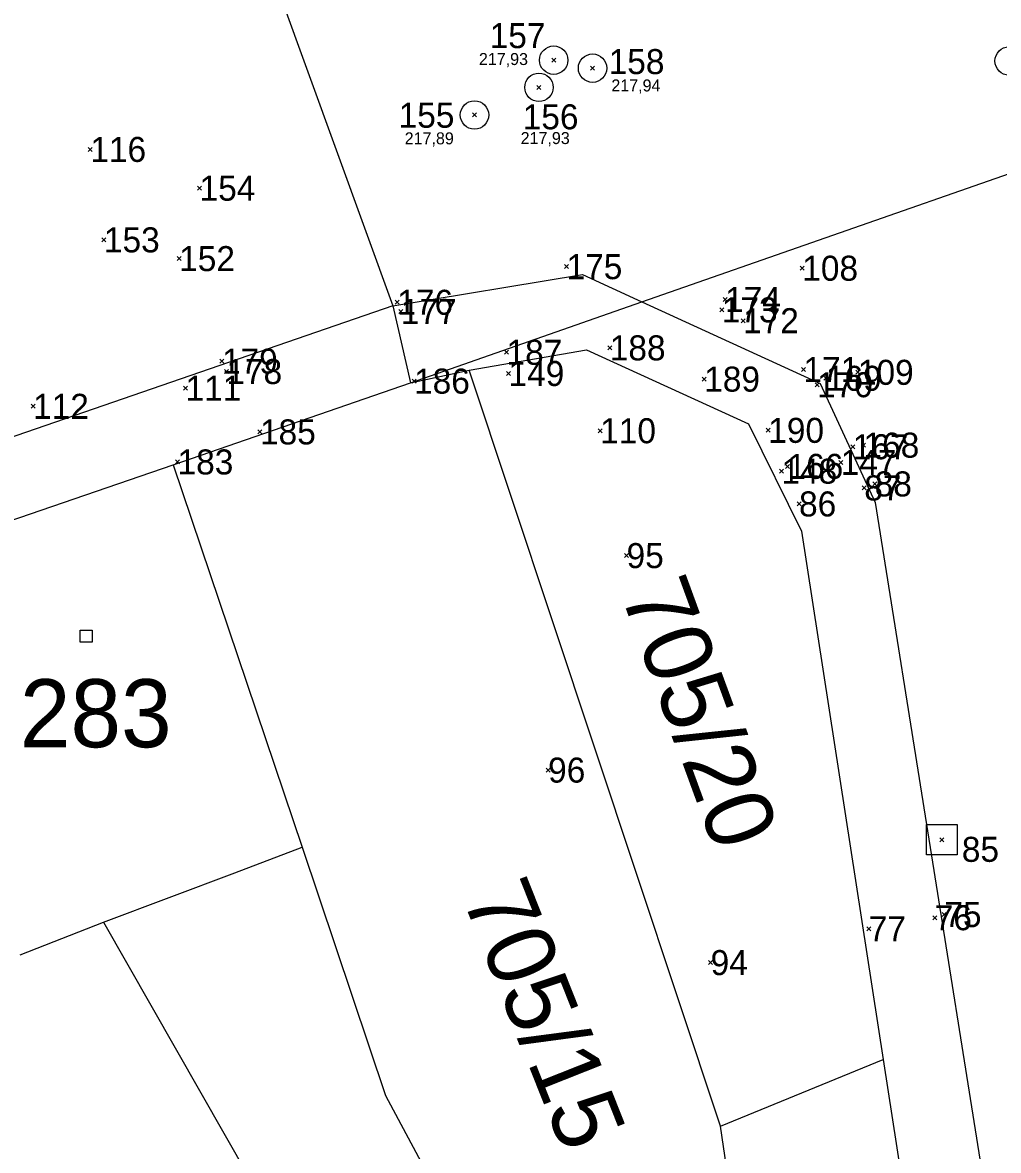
# Model space of a CAD drawing. Extents: x -711879 to -711361, y -1048782 to -1048177.
# Drawn here: x -711669.86 to -711645.48, y -1048569.9 to -1048541.72 of the extents above; entities that cross this region are included whole.
import ezdxf

# ---------------------------------------------------------------- set-up
doc = ezdxf.new("R2010")
doc.units = 0
for name, color, linetype in [('body', 7, 'Continuous'), ('kresba', 7, 'Continuous'), ('Vrstva 1', 7, 'Continuous'), ('Vrstva 14', 7, 'Continuous'), ('Vrstva 15', 7, 'Continuous'), ('Vrstva 2', 7, 'Continuous'), ('Vrstva 20', 7, 'Continuous'), ('Vrstva 25', 7, 'Continuous'), ('Vrstva 41', 7, 'Continuous'), ('Vrstva 46', 7, 'Continuous'), ('výšky', 7, 'Continuous')]:
    doc.layers.add(name, color=color, linetype=linetype)

msp = doc.modelspace()

# ---------------------------------------------------------------- linework, layer by layer
at = {"layer": 'kresba'}
msp.add_lwpolyline([(-711647.275, -1048561.76), (-711646.505, -1048561.76), (-711646.505, -1048562.52), (-711647.275, -1048562.52)], close=True, dxfattribs=at)
for centre in [(-711656.59, -1048542.66), (-711655.62, -1048542.86), (-711645.21, -1048542.68), (-711656.96, -1048543.34), (-711658.57, -1048544.03)]:
    msp.add_circle(centre, 0.355, dxfattribs=at)
at = {"layer": 'Vrstva 1'}
for p, q in [((-711664.62, -1048537.77), (-711660.61, -1048548.8)), ((-711654.39, -1048548.7), (-711637.91, -1048542.94)), ((-711660.61, -1048548.8), (-711660.17, -1048550.72)), ((-711660.17, -1048550.72), (-711654.39, -1048548.7)), ((-711654.39, -1048548.7), (-711649.93, -1048550.74)), ((-711658.7, -1048550.41), (-711655.77, -1048549.9)), ((-711655.77, -1048549.9), (-711651.72, -1048551.75)), ((-711660.17, -1048550.72), (-711658.7, -1048550.41)), ((-711652.42, -1048569.3), (-711658.7, -1048550.41)), ((-711666.1, -1048552.77), (-711660.17, -1048550.72)), ((-711649.93, -1048550.74), (-711648.56, -1048553.71)), ((-711651.72, -1048551.75), (-711650.4, -1048554.43)), ((-711673.96, -1048555.47), (-711666.1, -1048552.77)), ((-711666.1, -1048552.77), (-711662.88, -1048562.33)), ((-711648.56, -1048553.71), (-711625.71, -1048697.17)), ((-711650.4, -1048554.43), (-711648.36, -1048567.63)), ((-711662.88, -1048562.33), (-711660.79, -1048568.53)), ((-711652.42, -1048569.3), (-711648.36, -1048567.63)), ((-711648.36, -1048567.63), (-711645.9, -1048583.49)), ((-711660.79, -1048568.53), (-711658.99, -1048571.9)), ((-711650.24, -1048584.31), (-711652.42, -1048569.3))]:
    msp.add_line(p, q, dxfattribs=at)
at = {"layer": 'Vrstva 2'}
for p, q in [((-711660.61, -1048548.8), (-711655.87, -1048548.02)), ((-711655.87, -1048548.02), (-711654.39, -1048548.7)), ((-711660.61, -1048548.8), (-711673.32, -1048553.18)), ((-711664.56, -1048562.97), (-711662.88, -1048562.33)), ((-711667.84, -1048564.2), (-711664.56, -1048562.97)), ((-711669.92, -1048565.02), (-711667.84, -1048564.2)), ((-711667.84, -1048564.2), (-711661.64, -1048575.07))]:
    msp.add_line(p, q, dxfattribs=at)
at = {"layer": 'Vrstva 20'}
for p, q in [((-711656.59, -1048542.66), (-711656.64, -1048542.61)), ((-711656.59, -1048542.66), (-711656.64, -1048542.71)), ((-711656.59, -1048542.66), (-711656.54, -1048542.61)), ((-711656.59, -1048542.66), (-711656.54, -1048542.71)), ((-711655.62, -1048542.86), (-711655.67, -1048542.81)), ((-711655.62, -1048542.86), (-711655.67, -1048542.91)), ((-711655.62, -1048542.86), (-711655.57, -1048542.81)), ((-711655.62, -1048542.86), (-711655.57, -1048542.91)), ((-711656.96, -1048543.34), (-711657.01, -1048543.29)), ((-711656.96, -1048543.34), (-711657.01, -1048543.39)), ((-711656.96, -1048543.34), (-711656.91, -1048543.29)), ((-711656.96, -1048543.34), (-711656.91, -1048543.39)), ((-711658.57, -1048544.03), (-711658.62, -1048543.98)), ((-711658.57, -1048544.03), (-711658.52, -1048543.98)), ((-711658.57, -1048544.03), (-711658.62, -1048544.08)), ((-711658.57, -1048544.03), (-711658.52, -1048544.08)), ((-711668.17, -1048544.89), (-711668.22, -1048544.84)), ((-711668.17, -1048544.89), (-711668.12, -1048544.84)), ((-711668.17, -1048544.89), (-711668.22, -1048544.94)), ((-711668.17, -1048544.89), (-711668.12, -1048544.94)), ((-711665.44, -1048545.86), (-711665.49, -1048545.81)), ((-711665.44, -1048545.86), (-711665.49, -1048545.91)), ((-711665.44, -1048545.86), (-711665.39, -1048545.81)), ((-711665.44, -1048545.86), (-711665.39, -1048545.91)), ((-711667.83, -1048547.15), (-711667.88, -1048547.1)), ((-711667.83, -1048547.15), (-711667.78, -1048547.1)), ((-711667.83, -1048547.15), (-711667.88, -1048547.2)), ((-711667.83, -1048547.15), (-711667.78, -1048547.2)), ((-711665.95, -1048547.62), (-711666, -1048547.57)), ((-711665.95, -1048547.62), (-711666, -1048547.67)), ((-711665.95, -1048547.62), (-711665.9, -1048547.57)), ((-711665.95, -1048547.62), (-711665.9, -1048547.67)), ((-711656.27, -1048547.82), (-711656.32, -1048547.77)), ((-711656.27, -1048547.82), (-711656.32, -1048547.87)), ((-711656.27, -1048547.82), (-711656.22, -1048547.77)), ((-711656.27, -1048547.82), (-711656.22, -1048547.87)), ((-711650.38, -1048547.86), (-711650.43, -1048547.81)), ((-711650.38, -1048547.86), (-711650.43, -1048547.91)), ((-711650.38, -1048547.86), (-711650.33, -1048547.81)), ((-711650.38, -1048547.86), (-711650.33, -1048547.91)), ((-711660.5, -1048548.71), (-711660.55, -1048548.66)), ((-711660.5, -1048548.71), (-711660.55, -1048548.76)), ((-711660.5, -1048548.71), (-711660.45, -1048548.66)), ((-711660.5, -1048548.71), (-711660.45, -1048548.76)), ((-711652.31, -1048548.64), (-711652.36, -1048548.59)), ((-711652.31, -1048548.64), (-711652.36, -1048548.69)), ((-711652.31, -1048548.64), (-711652.26, -1048548.59)), ((-711652.31, -1048548.64), (-711652.26, -1048548.69)), ((-711660.41, -1048548.94), (-711660.46, -1048548.89)), ((-711660.41, -1048548.94), (-711660.46, -1048548.99)), ((-711660.41, -1048548.94), (-711660.36, -1048548.89)), ((-711660.41, -1048548.94), (-711660.36, -1048548.99)), ((-711652.39, -1048548.9), (-711652.44, -1048548.85)), ((-711652.39, -1048548.9), (-711652.44, -1048548.95)), ((-711652.39, -1048548.9), (-711652.34, -1048548.85)), ((-711652.39, -1048548.9), (-711652.34, -1048548.95)), ((-711651.86, -1048549.17), (-711651.91, -1048549.12)), ((-711651.86, -1048549.17), (-711651.91, -1048549.22)), ((-711651.86, -1048549.17), (-711651.81, -1048549.12)), ((-711651.86, -1048549.17), (-711651.81, -1048549.22)), ((-711657.77, -1048549.96), (-711657.82, -1048549.91)), ((-711657.77, -1048549.96), (-711657.72, -1048549.91)), ((-711655.19, -1048549.85), (-711655.24, -1048549.8)), ((-711655.19, -1048549.85), (-711655.24, -1048549.9)), ((-711655.19, -1048549.85), (-711655.14, -1048549.8)), ((-711655.19, -1048549.85), (-711655.14, -1048549.9)), ((-711664.88, -1048550.18), (-711664.93, -1048550.13)), ((-711664.88, -1048550.18), (-711664.93, -1048550.23)), ((-711664.88, -1048550.18), (-711664.83, -1048550.13)), ((-711664.88, -1048550.18), (-711664.83, -1048550.23)), ((-711657.77, -1048549.96), (-711657.82, -1048550.01)), ((-711657.77, -1048549.96), (-711657.72, -1048550.01)), ((-711664.77, -1048550.44), (-711664.82, -1048550.39)), ((-711664.77, -1048550.44), (-711664.82, -1048550.49)), ((-711664.77, -1048550.44), (-711664.72, -1048550.39)), ((-711664.77, -1048550.44), (-711664.72, -1048550.49)), ((-711657.72, -1048550.49), (-711657.77, -1048550.44)), ((-711657.72, -1048550.49), (-711657.77, -1048550.54)), ((-711657.72, -1048550.49), (-711657.67, -1048550.44)), ((-711657.72, -1048550.49), (-711657.67, -1048550.54)), ((-711650.35, -1048550.39), (-711650.4, -1048550.34)), ((-711650.35, -1048550.39), (-711650.4, -1048550.44)), ((-711650.35, -1048550.39), (-711650.3, -1048550.34)), ((-711650.35, -1048550.39), (-711650.3, -1048550.44)), ((-711648.99, -1048550.46), (-711649.04, -1048550.41)), ((-711648.99, -1048550.46), (-711649.04, -1048550.51)), ((-711648.99, -1048550.46), (-711648.94, -1048550.41)), ((-711648.99, -1048550.46), (-711648.94, -1048550.51)), ((-711660.08, -1048550.68), (-711660.13, -1048550.63)), ((-711660.08, -1048550.68), (-711660.13, -1048550.73)), ((-711660.08, -1048550.68), (-711660.03, -1048550.63)), ((-711660.08, -1048550.68), (-711660.03, -1048550.73)), ((-711652.83, -1048550.63), (-711652.88, -1048550.58)), ((-711652.83, -1048550.63), (-711652.88, -1048550.68)), ((-711652.83, -1048550.63), (-711652.78, -1048550.58)), ((-711652.83, -1048550.63), (-711652.78, -1048550.68)), ((-711650.01, -1048550.77), (-711650.06, -1048550.72)), ((-711650.01, -1048550.77), (-711650.06, -1048550.82)), ((-711650.01, -1048550.77), (-711649.96, -1048550.72)), ((-711650.01, -1048550.77), (-711649.96, -1048550.82)), ((-711649.79, -1048550.61), (-711649.84, -1048550.56)), ((-711649.79, -1048550.61), (-711649.84, -1048550.66)), ((-711649.79, -1048550.61), (-711649.74, -1048550.56)), ((-711649.79, -1048550.61), (-711649.74, -1048550.66)), ((-711665.79, -1048550.86), (-711665.84, -1048550.81)), ((-711665.79, -1048550.86), (-711665.84, -1048550.91)), ((-711665.79, -1048550.86), (-711665.74, -1048550.81)), ((-711665.79, -1048550.86), (-711665.74, -1048550.91)), ((-711669.6, -1048551.31), (-711669.65, -1048551.26)), ((-711669.6, -1048551.31), (-711669.65, -1048551.36)), ((-711669.6, -1048551.31), (-711669.55, -1048551.26)), ((-711669.6, -1048551.31), (-711669.55, -1048551.36)), ((-711663.93, -1048551.95), (-711663.98, -1048551.9)), ((-711663.93, -1048551.95), (-711663.88, -1048551.9)), ((-711655.43, -1048551.92), (-711655.48, -1048551.87)), ((-711655.43, -1048551.92), (-711655.38, -1048551.87)), ((-711651.23, -1048551.91), (-711651.28, -1048551.86)), ((-711651.23, -1048551.91), (-711651.18, -1048551.86)), ((-711663.93, -1048551.95), (-711663.98, -1048552)), ((-711663.93, -1048551.95), (-711663.88, -1048552)), ((-711655.43, -1048551.92), (-711655.48, -1048551.97)), ((-711655.43, -1048551.92), (-711655.38, -1048551.97)), ((-711651.23, -1048551.91), (-711651.28, -1048551.96)), ((-711651.23, -1048551.91), (-711651.18, -1048551.96)), ((-711649.12, -1048552.32), (-711649.17, -1048552.27)), ((-711649.12, -1048552.32), (-711649.17, -1048552.37)), ((-711649.12, -1048552.32), (-711649.07, -1048552.27)), ((-711649.12, -1048552.32), (-711649.07, -1048552.37)), ((-711648.85, -1048552.28), (-711648.9, -1048552.23)), ((-711648.85, -1048552.28), (-711648.9, -1048552.33)), ((-711648.85, -1048552.28), (-711648.8, -1048552.23)), ((-711648.85, -1048552.28), (-711648.8, -1048552.33)), ((-711665.99, -1048552.7), (-711666.04, -1048552.65)), ((-711665.99, -1048552.7), (-711666.04, -1048552.75)), ((-711665.99, -1048552.7), (-711665.94, -1048552.65)), ((-711665.99, -1048552.7), (-711665.94, -1048552.75)), ((-711649.42, -1048552.71), (-711649.47, -1048552.66)), ((-711649.42, -1048552.71), (-711649.47, -1048552.76)), ((-711649.42, -1048552.71), (-711649.37, -1048552.66)), ((-711649.42, -1048552.71), (-711649.37, -1048552.76)), ((-711650.9, -1048552.93), (-711650.95, -1048552.88)), ((-711650.9, -1048552.93), (-711650.95, -1048552.98)), ((-711650.9, -1048552.93), (-711650.85, -1048552.88)), ((-711650.9, -1048552.93), (-711650.85, -1048552.98)), ((-711650.75, -1048552.81), (-711650.8, -1048552.76)), ((-711650.75, -1048552.81), (-711650.8, -1048552.86)), ((-711650.75, -1048552.81), (-711650.7, -1048552.76)), ((-711650.75, -1048552.81), (-711650.7, -1048552.86)), ((-711648.83, -1048553.35), (-711648.88, -1048553.3)), ((-711648.83, -1048553.35), (-711648.78, -1048553.3)), ((-711648.57, -1048553.25), (-711648.62, -1048553.2)), ((-711648.57, -1048553.25), (-711648.62, -1048553.3)), ((-711648.57, -1048553.25), (-711648.52, -1048553.2)), ((-711648.57, -1048553.25), (-711648.52, -1048553.3)), ((-711648.83, -1048553.35), (-711648.88, -1048553.4)), ((-711648.83, -1048553.35), (-711648.78, -1048553.4)), ((-711650.46, -1048553.75), (-711650.51, -1048553.7)), ((-711650.46, -1048553.75), (-711650.51, -1048553.8)), ((-711650.46, -1048553.75), (-711650.41, -1048553.7)), ((-711650.46, -1048553.75), (-711650.41, -1048553.8)), ((-711654.77, -1048555.04), (-711654.82, -1048554.99)), ((-711654.77, -1048555.04), (-711654.72, -1048554.99)), ((-711654.77, -1048555.04), (-711654.82, -1048555.09)), ((-711654.77, -1048555.04), (-711654.72, -1048555.09)), ((-711656.73, -1048560.4), (-711656.78, -1048560.35)), ((-711656.73, -1048560.4), (-711656.68, -1048560.35)), ((-711656.73, -1048560.4), (-711656.78, -1048560.45)), ((-711656.73, -1048560.4), (-711656.68, -1048560.45)), ((-711646.89, -1048562.14), (-711646.94, -1048562.09)), ((-711646.89, -1048562.14), (-711646.94, -1048562.19)), ((-711646.89, -1048562.14), (-711646.84, -1048562.09)), ((-711646.89, -1048562.14), (-711646.84, -1048562.19)), ((-711646.83, -1048564.01), (-711646.88, -1048563.96)), ((-711646.83, -1048564.01), (-711646.88, -1048564.06)), ((-711646.83, -1048564.01), (-711646.78, -1048563.96)), ((-711646.83, -1048564.01), (-711646.78, -1048564.06)), ((-711647.07, -1048564.09), (-711647.12, -1048564.04)), ((-711647.07, -1048564.09), (-711647.12, -1048564.14)), ((-711647.07, -1048564.09), (-711647.02, -1048564.04)), ((-711647.07, -1048564.09), (-711647.02, -1048564.14)), ((-711648.72, -1048564.37), (-711648.77, -1048564.32)), ((-711648.72, -1048564.37), (-711648.77, -1048564.42)), ((-711648.72, -1048564.37), (-711648.67, -1048564.32)), ((-711648.72, -1048564.37), (-711648.67, -1048564.42)), ((-711652.67, -1048565.21), (-711652.72, -1048565.16)), ((-711652.67, -1048565.21), (-711652.72, -1048565.26)), ((-711652.67, -1048565.21), (-711652.62, -1048565.16)), ((-711652.67, -1048565.21), (-711652.62, -1048565.26))]:
    msp.add_line(p, q, dxfattribs=at)
at = {"layer": 'Vrstva 25'}
for p, q in [((-711668.42, -1048556.9), (-711668.12, -1048556.9)), ((-711668.42, -1048557.2), (-711668.42, -1048556.9)), ((-711668.12, -1048556.9), (-711668.12, -1048557.2)), ((-711668.12, -1048557.2), (-711668.42, -1048557.2))]:
    msp.add_line(p, q, dxfattribs=at)
at = {"layer": 'Vrstva 41'}
for p, q in [((-711656.59, -1048542.66), (-711656.59, -1048542.66)), ((-711655.62, -1048542.86), (-711655.62, -1048542.86)), ((-711656.96, -1048543.34), (-711656.96, -1048543.34)), ((-711658.57, -1048544.03), (-711658.57, -1048544.03)), ((-711668.17, -1048544.89), (-711668.17, -1048544.89)), ((-711665.44, -1048545.86), (-711665.44, -1048545.86)), ((-711667.83, -1048547.15), (-711667.83, -1048547.15)), ((-711665.95, -1048547.62), (-711665.95, -1048547.62)), ((-711656.27, -1048547.82), (-711656.27, -1048547.82)), ((-711650.38, -1048547.86), (-711650.38, -1048547.86)), ((-711660.5, -1048548.71), (-711660.5, -1048548.71)), ((-711652.31, -1048548.64), (-711652.31, -1048548.64)), ((-711660.41, -1048548.94), (-711660.41, -1048548.94)), ((-711652.39, -1048548.9), (-711652.39, -1048548.9)), ((-711651.86, -1048549.17), (-711651.86, -1048549.17)), ((-711655.19, -1048549.85), (-711655.19, -1048549.85)), ((-711664.88, -1048550.18), (-711664.88, -1048550.18)), ((-711657.77, -1048549.96), (-711657.77, -1048549.96)), ((-711664.77, -1048550.44), (-711664.77, -1048550.44)), ((-711657.72, -1048550.49), (-711657.72, -1048550.49)), ((-711650.35, -1048550.39), (-711650.35, -1048550.39)), ((-711648.99, -1048550.46), (-711648.99, -1048550.46)), ((-711660.08, -1048550.68), (-711660.08, -1048550.68)), ((-711652.83, -1048550.63), (-711652.83, -1048550.63)), ((-711650.01, -1048550.77), (-711650.01, -1048550.77)), ((-711649.79, -1048550.61), (-711649.79, -1048550.61)), ((-711665.79, -1048550.86), (-711665.79, -1048550.86)), ((-711669.6, -1048551.31), (-711669.6, -1048551.31)), ((-711663.93, -1048551.95), (-711663.93, -1048551.95)), ((-711655.43, -1048551.92), (-711655.43, -1048551.92)), ((-711651.23, -1048551.91), (-711651.23, -1048551.91)), ((-711649.12, -1048552.32), (-711649.12, -1048552.32)), ((-711648.85, -1048552.28), (-711648.85, -1048552.28)), ((-711665.99, -1048552.7), (-711665.99, -1048552.7)), ((-711649.42, -1048552.71), (-711649.42, -1048552.71)), ((-711650.9, -1048552.93), (-711650.9, -1048552.93)), ((-711650.75, -1048552.81), (-711650.75, -1048552.81)), ((-711648.57, -1048553.25), (-711648.57, -1048553.25)), ((-711648.83, -1048553.35), (-711648.83, -1048553.35)), ((-711650.46, -1048553.75), (-711650.46, -1048553.75)), ((-711654.77, -1048555.04), (-711654.77, -1048555.04)), ((-711656.73, -1048560.4), (-711656.73, -1048560.4)), ((-711646.89, -1048562.14), (-711646.89, -1048562.14)), ((-711646.83, -1048564.01), (-711646.83, -1048564.01)), ((-711647.07, -1048564.09), (-711647.07, -1048564.09)), ((-711648.72, -1048564.37), (-711648.72, -1048564.37)), ((-711652.67, -1048565.21), (-711652.67, -1048565.21))]:
    msp.add_line(p, q, dxfattribs=at)
at = {"layer": 'Vrstva 46'}
for p, q in [((-711660.61, -1048548.8), (-711660.61, -1048548.8)), ((-711658.7, -1048550.41), (-711658.7, -1048550.41)), ((-711660.17, -1048550.72), (-711660.17, -1048550.72)), ((-711666.1, -1048552.77), (-711666.1, -1048552.77)), ((-711664.56, -1048562.97), (-711664.56, -1048562.97)), ((-711667.84, -1048564.2), (-711667.84, -1048564.2)), ((-711648.36, -1048567.63), (-711648.36, -1048567.63)), ((-711660.79, -1048568.53), (-711660.79, -1048568.53))]:
    msp.add_line(p, q, dxfattribs=at)

# ---------------------------------------------------------------- texts
at = {"layer": 'body'}
for s, p in [('157', (-711658.191, -1048542.36)), ('158', (-711655.218, -1048543.009)), ('155', (-711660.466, -1048544.349)), ('156', (-711657.365, -1048544.388)), ('116', (-711668.17, -1048545.203)), ('154', (-711665.44, -1048546.172)), ('153', (-711667.83, -1048547.463)), ('152', (-711665.95, -1048547.932)), ('175', (-711656.27, -1048548.133)), ('108', (-711650.38, -1048548.172)), ('176', (-711660.5, -1048549.023)), ('174', (-711652.31, -1048548.953)), ('177', (-711660.41, -1048549.253)), ('173', (-711652.39, -1048549.213)), ('172', (-711651.86, -1048549.483)), ('187', (-711657.77, -1048550.273)), ('188', (-711655.19, -1048550.162)), ('179', (-711664.88, -1048550.493)), ('178', (-711664.77, -1048550.753)), ('149', (-711657.72, -1048550.802)), ('171', (-711650.35, -1048550.703)), ('109', (-711648.99, -1048550.773)), ('186', (-711660.08, -1048550.993)), ('189', (-711652.83, -1048550.943)), ('170', (-711650.01, -1048551.083)), ('169', (-711649.79, -1048550.922)), ('111', (-711665.79, -1048551.172)), ('112', (-711669.6, -1048551.623)), ('110', (-711655.43, -1048552.233)), ('190', (-711651.23, -1048552.223)), ('185', (-711663.93, -1048552.263)), ('167', (-711649.12, -1048552.633)), ('168', (-711648.85, -1048552.593)), ('183', (-711665.99, -1048553.013)), ('147', (-711649.42, -1048553.023)), ('148', (-711650.9, -1048553.243)), ('166', (-711650.75, -1048553.123)), ('87', (-711648.83, -1048553.662)), ('88', (-711648.57, -1048553.562)), ('86', (-711650.46, -1048554.062)), ('95', (-711654.77, -1048555.353)), ('96', (-711656.73, -1048560.713)), ('85', (-711646.393, -1048562.693)), ('75', (-711646.83, -1048564.323)), ('76', (-711647.07, -1048564.402)), ('77', (-711648.72, -1048564.682)), ('94', (-711652.67, -1048565.523))]:
    msp.add_text(s, height=0.625, dxfattribs=at).set_placement(p)
at = {"layer": 'Vrstva 14'}
for s, rotation, p in [('705/20', 290.1211, (-711654.93, -1048555.98)), ('705/15', 291.6392, (-711658.89, -1048563.57))]:
    msp.add_text(s, height=1.7, rotation=rotation, dxfattribs=at).set_placement(p)
at = {"layer": 'Vrstva 15'}
msp.add_text('283', height=1.7, dxfattribs=at).set_placement((-711669.93, -1048559.83))
at = {"layer": 'výšky'}
for s, p in [('217,93', (-711658.46, -1048542.782)), ('217,94', (-711655.15, -1048543.442)), ('217,89', (-711660.314, -1048544.764)), ('217,93', (-711657.417, -1048544.757))]:
    msp.add_text(s, height=0.3, dxfattribs=at).set_placement(p)

doc.saveas('drawing.dxf')
